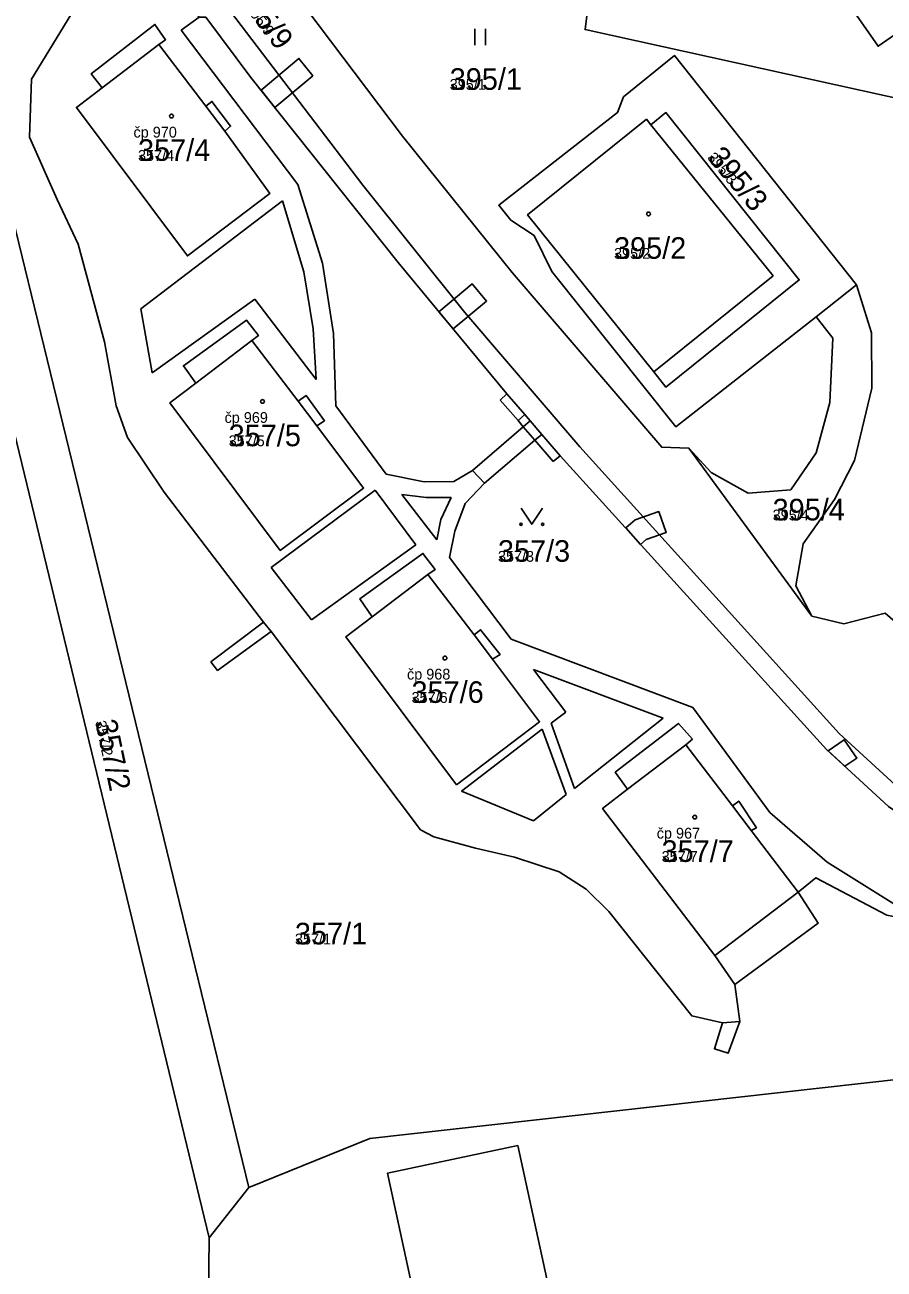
# Model space of a CAD drawing. Extents: x -763628 to -761565, y -976033 to -973833.
# Drawn here: x -762469.1 to -762389.5, y -974289.5 to -974174.3 of the extents above; entities that cross this region are included whole.
import ezdxf

# ---------------------------------------------------------------- set-up
doc = ezdxf.new("R2010")
doc.units = 0
for name, color, linetype in [('KN_cisla parcel 1000', 7, 'Continuous'), ('KN_cisla parcel 500', 7, 'Continuous'), ('KN_cisla popisna 500', 7, 'Continuous'), ('KN_hranice parcel', 7, 'Continuous'), ('KN_vecna bremena', 7, 'Continuous'), ('KN_vnitrni kresba parcel', 7, 'Continuous'), ('KN_znacky budov', 7, 'Continuous'), ('KN_znacky kultur', 7, 'Continuous')]:
    doc.layers.add(name, color=color, linetype=linetype)

msp = doc.modelspace()

# ---------------------------------------------------------------- linework, layer by layer
at = {"layer": 'KN_hranice parcel'}
for p, q in [((-762474.62, -974174.3), (-762448.38, -974281.95)), ((-762452.04, -974286.61), (-762478.91, -974175.72)), ((-762395.8, -974201.31), (-762392.06, -974198.32)), ((-762407.59, -974213.46), (-762396.18, -974229.03)), ((-762452.04, -974286.61), (-762448.38, -974281.95)), ((-762454.6, -974461.98), (-762452.04, -974286.61))]:
    msp.add_line(p, q, dxfattribs=at)
for points in [[(-762365.11, -974257.53), (-762371.55, -974255.8), (-762375.76, -974254.26), (-762378.06, -974253.26), (-762382.9, -974250.81), (-762389.07, -974246.65), (-762394.82, -974241.36), (-762419.52, -974214.16), (-762421.2, -974212.19), (-762422.29, -974210.92), (-762422.79, -974210.34), (-762424.46, -974208.44), (-762434.53, -974196.26), (-762448.17, -974179.14), (-762452.36, -974173.53), (-762452.98, -974173.55), (-762454.08, -974172.08), (-762453.71, -974171.81), (-762452.8, -974171.5), (-762451.41, -974171.89), (-762457.36, -974166.12), (-762458.33, -974166.67), (-762458.85, -974165.87)], [(-762447.47, -974165.72), (-762447.51, -974165.75), (-762447.29, -974166.06), (-762447.48, -974166.86), (-762434.13, -974184.55), (-762423.97, -974197.18), (-762410.09, -974213.37), (-762407.59, -974213.46)], [(-762393.51, -974168.7), (-762394.7, -974169.53), (-762390.05, -974176.24), (-762388.43, -974175.12), (-762387.87, -974177.06), (-762381.06, -974177.73), (-762382.71, -974175.16), (-762380.57, -974173.64), (-762378.43, -974176.65), (-762376.22, -974175.14), (-762376.01, -974173.85), (-762377.64, -974171.56), (-762375.23, -974169.84)], [(-762416.79, -974171.37), (-762417.2, -974174.69), (-762386.84, -974181.39)], [(-762403.31, -974263.13), (-762402.85, -974266.56), (-762403.94, -974269.5), (-762405.22, -974269.08), (-762404.46, -974266.67), (-762407.32, -974266.05), (-762415, -974256.36), (-762417.11, -974254.29), (-762419.62, -974252.69), (-762423.74, -974251.35), (-762427.35, -974250.5), (-762431.22, -974249.46), (-762432.46, -974248.8), (-762446.3, -974230.44), (-762451.26, -974234.05), (-762451.89, -974233.25), (-762447, -974229.57), (-762456.21, -974217.52), (-762459.61, -974212.47), (-762460.66, -974209.55), (-762461.75, -974203.62), (-762464.18, -974194.56), (-762466.14, -974190.43), (-762468.71, -974184.65), (-762468.5, -974179.28), (-762464.87, -974173.33)], [(-762461.97, -974180.09), (-762462.98, -974178.78), (-762457.08, -974174.21), (-762456.08, -974175.63), (-762456.72, -974176.07), (-762452.36, -974181.78), (-762451.79, -974181.35), (-762450.06, -974183.64), (-762450.58, -974184.1), (-762446.42, -974189.87), (-762454.06, -974195.66), (-762464.35, -974181.9), (-762461.97, -974180.09)], [(-762395.8, -974201.31), (-762408.78, -974211.48), (-762420.3, -974197.1), (-762421.91, -974193.77), (-762424.1, -974192.33), (-762425.21, -974190.96), (-762414.2, -974182.38), (-762413.65, -974180.92), (-762408.93, -974177.09), (-762392.06, -974198.32)], [(-762411.52, -974182.99), (-762422.53, -974191.84), (-762410.84, -974206.39), (-762409.71, -974207.81), (-762397.35, -974197.87), (-762409.71, -974182.38), (-762411.1, -974183.51), (-762411.52, -974182.99)], [(-762392.06, -974198.32), (-762390.65, -974202.79), (-762390.63, -974207.91), (-762392.23, -974214.61), (-762394.08, -974218.2), (-762396.98, -974222.31), (-762397.68, -974226.21), (-762396.18, -974229.03)], [(-762453.28, -974207.44), (-762454.44, -974205.83), (-762448.6, -974201.6), (-762447.48, -974203.03), (-762448.09, -974203.48), (-762443.81, -974209.11), (-762443.07, -974208.58), (-762441.36, -974210.92), (-762442.07, -974211.39), (-762437.73, -974217.16), (-762445.46, -974222.93), (-762455.69, -974209.27), (-762453.28, -974207.44)], [(-762407.59, -974213.46), (-762405.53, -974215.7), (-762402.08, -974217.63), (-762398.14, -974217.31), (-762395.79, -974213.9), (-762394.52, -974209.22), (-762394.23, -974203.27), (-762395.8, -974201.31)], [(-762429.13, -974244.64), (-762439.38, -974230.94), (-762436.93, -974229.07), (-762438.09, -974227.42), (-762432.24, -974223.2), (-762431.11, -974224.71), (-762431.77, -974225.15), (-762427.49, -974230.76), (-762426.89, -974230.28), (-762425.09, -974232.56), (-762425.79, -974232.99), (-762421.42, -974238.8), (-762429.13, -974244.64)], [(-762396.18, -974229.03), (-762393.21, -974229.72), (-762389.38, -974228.74), (-762386.39, -974231.33)], [(-762403.31, -974263.13), (-762405.18, -974260.46), (-762415.58, -974246.82), (-762413.26, -974245.05), (-762414.4, -974243.48), (-762408.55, -974238.95), (-762407.25, -974240.41), (-762407.86, -974240.93), (-762403.54, -974246.59), (-762402.96, -974246.15), (-762401.32, -974248.61), (-762401.8, -974248.87), (-762397.46, -974254.58)], [(-762365.11, -974257.53), (-762371.47, -974257.71), (-762385.26, -974257.53), (-762389.25, -974256.72), (-762395.83, -974253.24), (-762397.46, -974254.58)], [(-762397.46, -974254.58), (-762395.6, -974257.46), (-762403.31, -974263.13)], [(-762448.38, -974281.95), (-762437.16, -974277.41), (-762349.71, -974267.62), (-762349.42, -974267.56)], [(-762423.43, -974278.04), (-762435.52, -974280.61), (-762427.85, -974315.96), (-762415.74, -974313.41), (-762423.43, -974278.04)]]:
    msp.add_lwpolyline(points, dxfattribs=at)
at = {"layer": 'KN_vecna bremena'}
for points in [[(-762447.23, -974180.31), (-762445.96, -974181.92), (-762442.45, -974178.96), (-762443.73, -974177.36)], [(-762430.75, -974200.84), (-762429.44, -974202.42), (-762426.34, -974199.83), (-762427.66, -974198.25)], [(-762412.07, -974222.37), (-762411.53, -974221.93), (-762409.69, -974221.28), (-762410.37, -974219.34), (-762412.57, -974220.11), (-762413.44, -974220.85)], [(-762393.12, -974242.92), (-762392.03, -974242.18), (-762393.18, -974240.48), (-762394.68, -974241.49)]]:
    msp.add_lwpolyline(points, close=True, dxfattribs=at)
at = {"layer": 'KN_vnitrni kresba parcel'}
for p, q in [((-762454.63, -974174.73), (-762452.98, -974173.55)), ((-762450.06, -974173), (-762437.8, -974189.1)), ((-762443.82, -974189.05), (-762454.63, -974174.73)), ((-762461.97, -974180.09), (-762456.72, -974176.07)), ((-762450.58, -974184.1), (-762452.36, -974181.78)), ((-762399.77, -974197.51), (-762411.1, -974183.51)), ((-762441.53, -974196.32), (-762443.82, -974189.05)), ((-762437.8, -974189.1), (-762428.35, -974200.88)), ((-762458.38, -974200.55), (-762445.24, -974190.54)), ((-762445.24, -974190.54), (-762443.27, -974197.12)), ((-762440.51, -974202.84), (-762441.53, -974196.32)), ((-762443.27, -974197.12), (-762442.4, -974202.41)), ((-762410.84, -974206.39), (-762399.77, -974197.51)), ((-762447.8, -974199.67), (-762457.32, -974206.49)), ((-762442.14, -974207.09), (-762447.8, -974199.67)), ((-762457.32, -974206.49), (-762458.38, -974200.55)), ((-762428.35, -974200.88), (-762417.69, -974213.35)), ((-762442.4, -974202.41), (-762442.14, -974207.09)), ((-762440.31, -974209.55), (-762440.51, -974202.84)), ((-762453.28, -974207.44), (-762448.09, -974203.48)), ((-762424.46, -974208.44), (-762425.07, -974209)), ((-762442.07, -974211.39), (-762443.81, -974209.11)), ((-762435.64, -974215.87), (-762440.31, -974209.55)), ((-762425.07, -974209), (-762423.42, -974210.9)), ((-762423.42, -974210.9), (-762422.79, -974210.34)), ((-762422.93, -974211.47), (-762423.42, -974210.9)), ((-762422.93, -974211.47), (-762427.65, -974215.54)), ((-762422.29, -974210.92), (-762422.93, -974211.47)), ((-762421.86, -974212.72), (-762422.93, -974211.47)), ((-762426.53, -974216.71), (-762421.86, -974212.72)), ((-762421.86, -974212.72), (-762421.2, -974212.19)), ((-762421.86, -974212.72), (-762420.15, -974214.7)), ((-762419.52, -974214.16), (-762420.15, -974214.7)), ((-762417.69, -974213.35), (-762393.64, -974239.88)), ((-762432.13, -974216.57), (-762435.64, -974215.87)), ((-762429.37, -974216.54), (-762432.13, -974216.57)), ((-762427.65, -974215.54), (-762429.37, -974216.54)), ((-762426.53, -974216.71), (-762427.65, -974215.54)), ((-762446.3, -974224.51), (-762436.66, -974217.36)), ((-762436.66, -974217.36), (-762432.88, -974222.4)), ((-762434.19, -974217.75), (-762431.94, -974218.04)), ((-762430.96, -974221.94), (-762434.19, -974217.75)), ((-762428.33, -974218.57), (-762426.53, -974216.71)), ((-762431.94, -974218.04), (-762429.61, -974218.02)), ((-762429.61, -974218.02), (-762430.58, -974220.08)), ((-762429.28, -974221.16), (-762428.33, -974218.57)), ((-762430.58, -974220.08), (-762430.96, -974221.94)), ((-762429.76, -974223.59), (-762429.28, -974221.16)), ((-762432.88, -974222.4), (-762442.57, -974229.37)), ((-762424.06, -974231.16), (-762429.76, -974223.59)), ((-762442.57, -974229.37), (-762446.3, -974224.51)), ((-762436.93, -974229.07), (-762431.77, -974225.15)), ((-762446.3, -974230.44), (-762447, -974229.57)), ((-762425.79, -974232.99), (-762427.49, -974230.76)), ((-762407.22, -974237.48), (-762424.06, -974231.16)), ((-762421.97, -974233.97), (-762409.98, -974238.46)), ((-762418.99, -974237.92), (-762421.97, -974233.97)), ((-762420.36, -974238.93), (-762418.99, -974237.92)), ((-762409.98, -974238.46), (-762418.18, -974244.99)), ((-762400.08, -974247.19), (-762407.22, -974237.48)), ((-762428.67, -974245.23), (-762421.17, -974239.5)), ((-762421.17, -974239.5), (-762418.96, -974245.54)), ((-762418.18, -974244.99), (-762420.36, -974238.93)), ((-762393.64, -974239.88), (-762387.73, -974245.32)), ((-762413.26, -974245.05), (-762407.86, -974240.93)), ((-762421.99, -974247.98), (-762428.67, -974245.23)), ((-762418.96, -974245.54), (-762421.99, -974247.98)), ((-762401.8, -974248.87), (-762403.54, -974246.59)), ((-762394.76, -974251.79), (-762400.08, -974247.19)), ((-762388.34, -974255.83), (-762394.76, -974251.79)), ((-762405.18, -974260.46), (-762397.46, -974254.58)), ((-762404.46, -974266.67), (-762402.85, -974266.56))]:
    msp.add_line(p, q, dxfattribs=at)
at = {"layer": 'KN_znacky budov'}
for centre in [(-762455.54, -974182.7), (-762411.32, -974191.77), (-762447.1, -974209.13), (-762430.19, -974232.9), (-762407.04, -974247.63)]:
    msp.add_circle(centre, 0.175, dxfattribs=at)
at = {"layer": 'KN_znacky kultur'}
for p, q in [((-762427.42, -974176.12), (-762427.42, -974174.62)), ((-762426.42, -974176.12), (-762426.42, -974174.62))]:
    msp.add_line(p, q, dxfattribs=at)
msp.add_lwpolyline([(-762423.14, -974219.01), (-762422.14, -974220.51), (-762421.14, -974219.01)], dxfattribs=at)
for centre in [(-762423.14, -974220.51), (-762421.14, -974220.51)]:
    msp.add_circle(centre, 0.1, dxfattribs=at)

# ---------------------------------------------------------------- texts
at = {"layer": 'KN_cisla parcel 1000'}
for s, rotation, p in [('395/9', 307, (-762449.73, -974171.38)), ('395/3', 310, (-762405.94, -974186.57)), ('357/2', 282, (-762462.62, -974238.8))]:
    msp.add_text(s, height=2, rotation=rotation, dxfattribs=at).set_placement(p)
for s, p in [('395/1', (-762429.75, -974180.27)), ('357/4', (-762458.64, -974186.85)), ('395/2', (-762414.52, -974195.92)), ('357/5', (-762450.24, -974213.28)), ('395/4', (-762399.82, -974220.15)), ('357/3', (-762425.28, -974223.98)), ('357/6', (-762433.29, -974237.05)), ('357/7', (-762410.11, -974251.78)), ('357/1', (-762444.1, -974259.42))]:
    msp.add_text(s, height=2, dxfattribs=at).set_placement(p)
at = {"layer": 'KN_cisla parcel 500'}
for s, rotation, p in [('395/9', 307, (-762448.75, -974172.68)), ('395/3', 310, (-762405.94, -974186.57)), ('357/2', 282, (-762462.62, -974238.8))]:
    msp.add_text(s, height=1, rotation=rotation, dxfattribs=at).set_placement(p)
for s, p in [('395/1', (-762429.75, -974180.27)), ('357/4', (-762458.64, -974186.85)), ('395/2', (-762414.52, -974195.92)), ('357/5', (-762450.24, -974213.28)), ('395/4', (-762399.82, -974220.15)), ('357/3', (-762425.28, -974223.98)), ('357/6', (-762433.29, -974237.05)), ('357/7', (-762410.11, -974251.78)), ('357/1', (-762444.1, -974259.42))]:
    msp.add_text(s, height=1, dxfattribs=at).set_placement(p)
at = {"layer": 'KN_cisla popisna 500'}
for s, p in [('čp 970', (-762459.06, -974184.69)), ('čp 969', (-762450.62, -974211.12)), ('čp 968', (-762433.71, -974234.89)), ('čp 967', (-762410.56, -974249.62))]:
    msp.add_text(s, height=1, dxfattribs=at).set_placement(p)

doc.saveas('drawing.dxf')
